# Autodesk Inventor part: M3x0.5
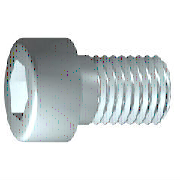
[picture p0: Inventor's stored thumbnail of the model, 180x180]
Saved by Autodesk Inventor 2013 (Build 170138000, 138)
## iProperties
Created: 2009-02
Part Number: M3x0.5
Material: 강, 연강
Description: 6각머리 태핑 나사
Document SubType Name: Modeling
Standard: KS B 1003
Designer: 한국산업디자인학원-SeoGD™
Standards Organization: KS
Language: ko-KR
Size Designation: M 3 x 6
Categories: <MemberInstance><Categories><Category DisplayName="조임쇠" InternalName="e4da775c-781d-43d5-af7c-5136215cf5a6" Mnemonic="FSTN"><Category DisplayName="볼트" InternalN
Density: 7.86 g/cm^3
Mass: 0.818725 g
Surface Area: 1.64152 cm^2
Volume: 0.104163 cm^3
IsCustomPart: 1
Author: 진현석
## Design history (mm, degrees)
sketch "스케치1"
  geometry: L1 (-0.867, 0)-(12, 0); L2 (12, 0)-(12, 1.5); L3 (12, 1.5)-(1, 1.5); L4 (1, 1.5)-(0.693, 1.5); L5 (0.693, 1.5)-(0, 1.5); L6 (0, 1.5)-(0, 2.75); L7 (0, 2.75)-(-3, 2.75); L8 (-3, 2.75)-(-3, 1.443); L9 (-3, 1.443)-(-1.7, 1.443); L10 (-1.7, 1.443)-(-0.867, 0); L11 (-6, 0)-(15, 0) reference; L12 (0, -0.55)-(0, 3.3) reference; L13 (1, 1.5)-(0, 1.5)
  constraints: 22 end point, 6 parallel, 2 collinear, 2 perpendicular, 1 horizontal, 1 point on line
  dimensions: "d1" = 11 distance from line of L3.end L2; "d2" = 0.30683 distance of L4.end L3.end (computed from GAL); "d3" = 3 distance between parallel lines of L8 L6 (= KOH); "d4" = 1.3 distance of L8.end L9.end (= INTI); "d5" = 60 deg angle of L10 L1; "d6" = 3 diameter of L3 L1 (= GD); "d7" = 3 diameter of L5 L1 (= BDM); "d8" = 2.88675 diameter of L9 L1 (= 1.1547 x SW); "d9" = 5.5 diameter of L7 L1 (= KOD); "d26" = 12 distance between parallel lines of L12 L2
revolve "본체" sketch "스케치1" stored, may be unused: angle "d10" = 90 deg
sketch "스케치2"
  geometry: L1 (0, -3.85)-(0, 3.85) reference; L2 (-3.85, 0)-(3.85, 0) reference; L3 (1.443, 0)-(0.722, -1.25); L4 (0.722, -1.25)-(-0.722, -1.25); L5 (-0.722, -1.25)-(-1.443, 0); L6 (-1.443, 0)-(-0.722, 1.25); L7 (-0.722, 1.25)-(0.722, 1.25); L8 (0.722, 1.25)-(1.443, 0); 2 further points
  constraints: 12 end point, 1 coincident, 1 horizontal alignment, 1 point on line, 12 other
extrude "슬롯" join sketch "스케치2" stored distance "d11" = 10; taper "d12" = 0 deg
workplane "Work Plane1"
fillet "Fillet2" dims "d30" = 0.1 (= R)
body "Solid1"
fillet "모깎기1" dims "d17" = 0.3 (= RR)
feature "스레드" dims "d13" = 11, "d14" = 0
chamfer "모따기1" distance "d15" = 0.30673 (= -0.5 x SPD + 0.5 x GD); stored, may be unused: second distance "d16" = 0.30673 (= GUL), angle "d27" = 45 deg
other parameters: "GD" = 3 (= NND) [user parameter; used in 2 equation terms], "NLG" = 6 [user parameter], "GEL" = 4.75 [user parameter], "KOD" = 5.5 [user parameter; used in 1 equation term], "KOH" = 3 [user parameter; used in 1 equation term], "INTI" = 1.3 [user parameter; used in 1 equation term], "GAL" = 0.30673 (= 0.61345 x PTC) [user parameter; used in 1 equation term], "GUL" = 0.30673 (= 0.61345 x PTC) [user parameter; used in 1 equation term], "BDM" = 3 (= NND) [user parameter; used in 1 equation term], "SW" = 2.5 [user parameter; used in 2 equation terms], "RR" = 0.3 [user parameter; used in 1 equation term], "SPD" = 2.38655 (= NND - 1.2269 x PTC) [user parameter; used in 1 equation term], "d19" = 0, "d28" = 0, "d29" = 0, "R" = 0.1 [user parameter; used in 1 equation term], "PHH" = 0.1 [user parameter], "GD1" = 2.38655 (= THREADDIA - 1.2269 x PTC) [user parameter], "THREADDIA" = 3 [user parameter; used in 1 equation term], "FAWI" = 45 deg [user parameter], "PTC" = 0.5 [user parameter; used in 5 equation terms], "NND" = 3 [user parameter; used in 3 equation terms], "TOA" = 30 deg [user parameter], "E0" = 2.8875 (= 1.155 x SW) [user parameter]
